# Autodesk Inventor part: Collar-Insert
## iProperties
Shininess: 64.0
Length Units: 11269
Angle Units: 11279
Time Units: 11290
Mass Units: 11283
Length Display Precision: 3
Angle Display Precision: 2
Compacted: True
Part Number: Collar-Insert
Document SubType Name: Modeling
Created: 2004-01
Designer: Administrator
Manufacturer: Standard
Standards Organization: Custom
Density: 1 g/cm^3
Density: 0.0
Volumn: 0.0
Area: 0.0
PropertySet Name: Model Information
Control State: 0
Master: False
Checked Out: False
Author: Administrator
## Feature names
1. Revolution1
2. Chamfer1
3. Chamfer2
4. Hole1
5. Circular Pattern1
6. Hole2
7. Circular Pattern2
8. Chamfer3
